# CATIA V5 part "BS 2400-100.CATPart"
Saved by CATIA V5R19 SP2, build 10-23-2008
Part number: BS 2400-100
Bounding box of the stored display mesh (mm): x -37.351 to 37.351, y -37.351 to 37.351, z 0 to 245
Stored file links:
  C:\Users\Bora\Desktop\3D Katı model\BS serisi\BS 2400\BS 2400-100.CATPart
  C:\Program Files\Dassault Systemes\B19\intel_a\reffiles\standard\MetricThickPitch.txt
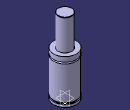
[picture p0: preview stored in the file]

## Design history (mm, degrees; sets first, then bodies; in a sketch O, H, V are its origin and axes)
Body1 (main body)
  Sketch1 on yz-plane, origin (0, 0, 0), H (0, 1, 0), V (0, 0, 1)
    point P1 (22.5, 244)
    point P3 (22.5, 244)
    point P7 (37.5, 128.5)
    point P9 (37.5, 128.5)
    point P10 (37.5, 123.5)
    point P14 (37.5, 123.5)
    line L1 (22.5, 244) -> (22.5, 144)
    arc A1 centre (21.5, 244) radius 1 from (22.5, 244) to (21.5, 245) ccw
    line L2 (37.5, 0) -> (37.5, 8)
    line L3 (37.5, 128.5) -> (37.5, 144)
    arc A2 centre (37.5, 126) radius 2.5 from (37.5, 128.5) to (37.5, 123.5) ccw
    line L4 (34.5, 13) -> (34.5, 8)
    line L5 (37.5, 13) -> (37.5, 123.5)
    line L6 (21.5, 245) -> (0, 245)
    point P15 (0, 245)
    line L7 (22.5, 144) -> (37.5, 144)
    line L8 (0, 0) -> (37.5, 0)
    line L9 (34.5, 13) -> (37.5, 13)
    line L10 (34.5, 8) -> (37.5, 8)
    coincidence: P15 V, P1 P3, P7 P9, P10 P14
    tangency: L6 A1
    horizontal: L7 H, L8 H, L9 H, L10 H
  Shaft1: profile Sketch1, axis Sketch1.V, angle 360
  Sketch2 on face of Shaft1 from Sketch1.L8, origin (0, 0, 0), H (1, 0, 0), V (0, -1, 0)
    point P1 (20, 0)
    distance P1 V = 20
  Hole1: placed by Sketch2, at (20, 0, 0) direction (0, 0, 1), diameter 6.647, depth 5, threaded "M8", thread diameter 8, thread depth 5, pitch 1.25
  CircPattern1: of Hole1, instances 4, angular step 90, axis from xy-plane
